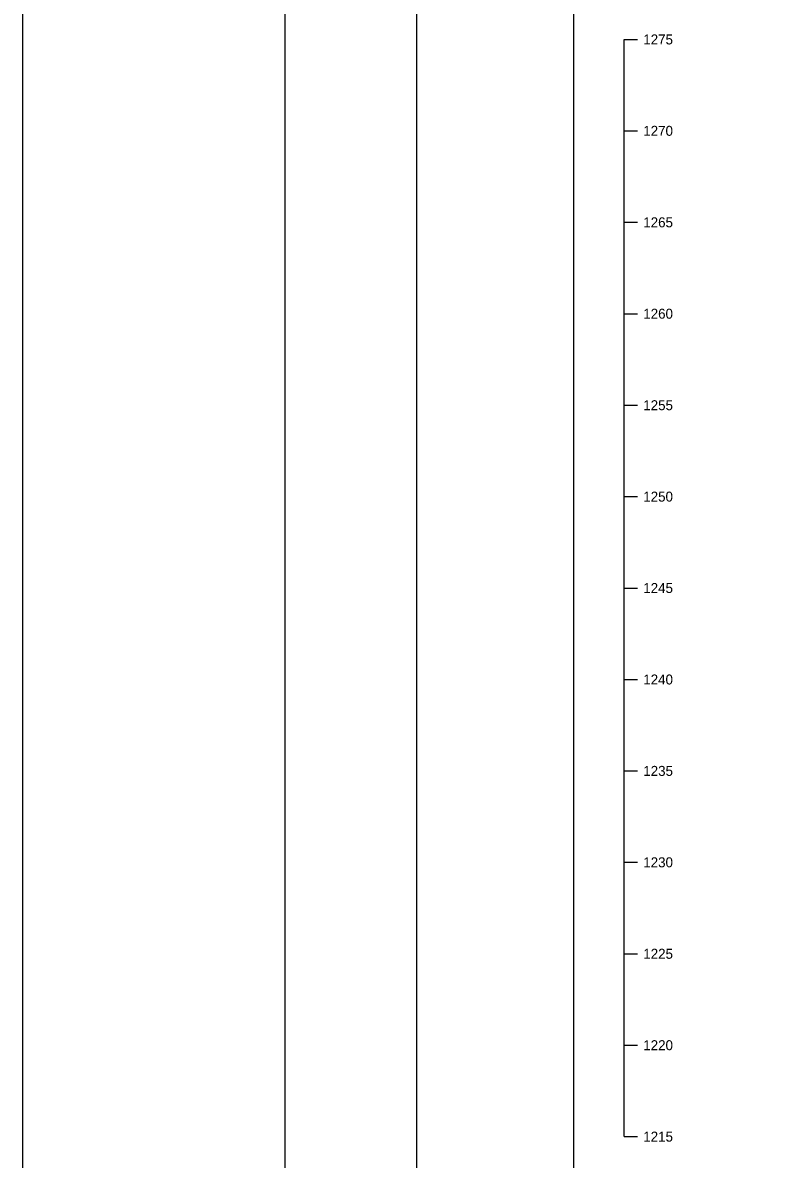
# Model space of a CAD drawing. Extents: x 2150161.5 to 2150203.1, y 143779.5 to 143868.5.
# Drawn here: x 2150161.53 to 2150170.94, y 143842.21 to 143856.33 of the extents above; entities that cross this region are included whole.
import ezdxf

# ---------------------------------------------------------------- set-up
doc = ezdxf.new("R2010")
doc.units = 0
for name, color, linetype in [('Default', 7, 'Continuous'), ('S', 7, 'Continuous'), ('SHT_Plot_Shape_Full', 7, 'Continuous'), ('SHT_Plot_Shape_Half', 7, 'Continuous'), ('SHT_Sheet_Border', 7, 'Continuous')]:
    doc.layers.add(name, color=color, linetype=linetype)

msp = doc.modelspace()

# ---------------------------------------------------------------- linework, layer by layer
at = {"layer": 'Default'}
msp.add_line((2150169.005, 143842.487), (2150169.005, 143856.123), dxfattribs=at)
for points in [[(2150169.005, 143856.123), (2150169.171, 143856.123)], [(2150169.005, 143854.987), (2150169.171, 143854.987)], [(2150169.005, 143853.85), (2150169.171, 143853.85)], [(2150169.005, 143852.714), (2150169.171, 143852.714)], [(2150169.005, 143851.577), (2150169.171, 143851.577)], [(2150169.005, 143850.441), (2150169.171, 143850.441)], [(2150169.005, 143849.305), (2150169.171, 143849.305)], [(2150169.005, 143848.168), (2150169.171, 143848.168)], [(2150169.005, 143847.032), (2150169.171, 143847.032)], [(2150169.005, 143845.896), (2150169.171, 143845.896)], [(2150169.005, 143844.759), (2150169.171, 143844.759)], [(2150169.005, 143843.623), (2150169.171, 143843.623)], [(2150169.005, 143842.487), (2150169.171, 143842.487)]]:
    msp.add_lwpolyline(points, dxfattribs=at)
at = {"layer": 'S'}
msp.add_lwpolyline([(2150161.53, 143868.477), (2150203.071, 143868.477), (2150203.071, 143779.536), (2150161.53, 143779.536)], close=True, dxfattribs=at)
at = {"layer": 'SHT_Plot_Shape_Full'}
msp.add_lwpolyline([(2150164.792, 143860.145), (2150200.792, 143860.145), (2150200.792, 143836.145), (2150164.792, 143836.145)], close=True, dxfattribs=at)
at = {"layer": 'SHT_Plot_Shape_Half'}
msp.add_lwpolyline([(2150166.429, 143859.32), (2150200.429, 143859.32), (2150200.429, 143837.32), (2150166.429, 143837.32)], close=True, dxfattribs=at)
at = {"layer": 'SHT_Sheet_Border'}
msp.add_lwpolyline([(2150199.879, 143837.82), (2150168.379, 143837.82), (2150168.379, 143858.82), (2150199.879, 143858.82)], close=True, dxfattribs=at)

# ---------------------------------------------------------------- texts
at = {"layer": 'Default'}
for s, p in [('1275', (2150169.242, 143856.061)), ('1270', (2150169.242, 143854.925)), ('1265', (2150169.242, 143853.788)), ('1260', (2150169.242, 143852.652)), ('1255', (2150169.242, 143851.515)), ('1250', (2150169.242, 143850.379)), ('1245', (2150169.242, 143849.243)), ('1240', (2150169.242, 143848.106)), ('1235', (2150169.242, 143846.97)), ('1230', (2150169.242, 143845.834)), ('1225', (2150169.242, 143844.697)), ('1220', (2150169.242, 143843.561)), ('1215', (2150169.242, 143842.425))]:
    msp.add_text(s, height=0.124, dxfattribs=at).set_placement(p)

doc.saveas('drawing.dxf')
